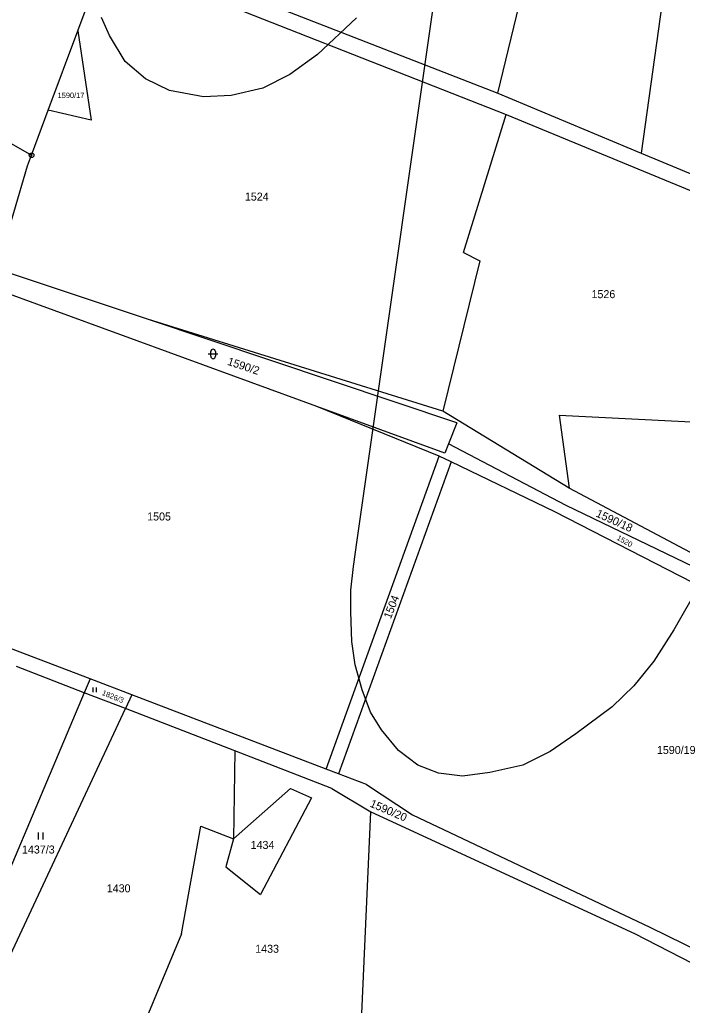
# Model space of a CAD drawing. Extents: x -546762 to -540209, y -1046851 to -1035694.
# Drawn here: x -543447.5 to -543306.6, y -1041018.4 to -1040809.1 of the extents above; entities that cross this region are included whole.
import ezdxf

# ---------------------------------------------------------------- set-up
doc = ezdxf.new("R2010")
doc.units = 0
for name, color, linetype in [('Vrstva 1', 7, 'Continuous'), ('Vrstva 18', 7, 'Continuous'), ('Vrstva 24', 7, 'Continuous'), ('Vrstva 25', 7, 'Continuous'), ('Vrstva 52', 7, 'Continuous'), ('Vrstva 6', 7, 'Continuous')]:
    doc.layers.add(name, color=color, linetype=linetype)

msp = doc.modelspace()

# ---------------------------------------------------------------- linework, layer by layer
at = {"layer": 'Vrstva 1'}
for points in [[(-543435.13, -1040811.43), (-543428.68, -1040794.07)], [(-543441.39, -1040828.27), (-543435.13, -1040811.43)], [(-543473.34, -1040821.64), (-543444.94, -1040837.84)], [(-543444.94, -1040837.84), (-543441.39, -1040828.27)], [(-543445.79, -1040840.11), (-543444.94, -1040837.84)], [(-543451.66, -1040859.91), (-543445.79, -1040840.11)], [(-543420.32, -1040872.69), (-543452.28, -1040862.01)], [(-543384.31, -1040891.22), (-543454.19, -1040865.7)], [(-543354.57, -1040894.66), (-543420.32, -1040872.69)], [(-543357.1, -1040901.15), (-543384.31, -1040891.22)], [(-543354.57, -1040894.66), (-543356.32, -1040899.16)], [(-543356.32, -1040899.16), (-543357.1, -1040901.15)], [(-543432.51, -1040949.06), (-543456.92, -1040939.75)], [(-543433.75, -1040951.99), (-543448.12, -1040946.45)], [(-543432.51, -1040949.06), (-543433.75, -1040951.99)], [(-543423.63, -1040952.45), (-543432.51, -1040949.06)], [(-543433.75, -1040951.99), (-543460.13, -1041014.34)], [(-543425, -1040955.37), (-543433.75, -1040951.99)], [(-543423.63, -1040952.45), (-543425, -1040955.37)], [(-543454.04, -1041017.4), (-543425, -1040955.37)]]:
    msp.add_lwpolyline(points, dxfattribs=at)
at = {"layer": 'Vrstva 24'}
for radius in [0.5, 0.1]:
    msp.add_circle((-543444.94, -1040837.84), radius, dxfattribs=at)
at = {"layer": 'Vrstva 25'}
for p, q in [((-543407.38, -1040880.05), (-543405.38, -1040880.05)), ((-543406.88, -1040880.55), (-543406.88, -1040879.55)), ((-543405.88, -1040879.55), (-543405.88, -1040880.55)), ((-543431.84, -1040951.91), (-543431.84, -1040950.91)), ((-543431.18, -1040951.91), (-543431.18, -1040950.91)), ((-543443.49, -1040983.2), (-543443.49, -1040981.7)), ((-543442.49, -1040983.2), (-543442.49, -1040981.7))]:
    msp.add_line(p, q, dxfattribs=at)
for centre, start, end in [((-543406.38, -1040879.55), 0, 180), ((-543406.38, -1040880.55), 180, 0)]:
    msp.add_arc(centre, 0.5, start, end, dxfattribs=at)
at = {"layer": 'Vrstva 52'}
for points in [[(-543303.12, -1040929.34), (-543308.45, -1040938.67), (-543312.69, -1040945.33), (-543316.93, -1040950.54), (-543321.53, -1040955.03), (-543329.28, -1040960.72), (-543334.73, -1040964.48), (-543340.54, -1040967.39), (-543347.57, -1040968.96), (-543353.38, -1040969.69), (-543358.47, -1040969.08), (-543362.83, -1040967.39), (-543366.94, -1040964.24), (-543370.58, -1040959.87), (-543372.88, -1040956.12), (-543374.69, -1040951.39), (-543376.15, -1040946.06), (-543376.87, -1040941.09), (-543377.12, -1040934.79), (-543377.12, -1040930.19), (-543376.51, -1040925.22), (-543375.75, -1040919.57), (-543356.78, -1040786.63)], [(-543375.91, -1040808.69), (-543384.15, -1040816.44), (-543390.08, -1040820.68), (-543395.78, -1040823.59), (-543402.56, -1040825.17), (-543408.37, -1040825.41), (-543415.64, -1040824.08), (-543420.72, -1040821.65), (-543425.08, -1040817.9), (-543428.35, -1040812.44), (-543430.05, -1040808.57)]]:
    msp.add_lwpolyline(points, dxfattribs=at)
at = {"layer": 'Vrstva 6'}
for points in [[(-543345.87, -1040824.69), (-543328.21, -1040751.86)], [(-543304.84, -1040761.68), (-543315.35, -1040837.41)], [(-543420.75, -1040795.46), (-543345.87, -1040824.69)], [(-543420.93, -1040798.94), (-543344.09, -1040829.21)], [(-543435.13, -1040811.43), (-543432.28, -1040830.42)], [(-543345.87, -1040824.69), (-543315.35, -1040837.41)], [(-543432.28, -1040830.42), (-543441.39, -1040828.27)], [(-543353.18, -1040858.52), (-543344.09, -1040829.21)], [(-543344.09, -1040829.21), (-543288.97, -1040851.94)], [(-543315.35, -1040837.41), (-543287.43, -1040849.04)], [(-543353.18, -1040858.52), (-543349.67, -1040860.25)], [(-543349.67, -1040860.25), (-543357.56, -1040892.17)], [(-543357.56, -1040892.17), (-543420.32, -1040872.69)], [(-543358.35, -1040901.76), (-543384.31, -1040891.22)], [(-543330.72, -1040908.55), (-543357.56, -1040892.17)], [(-543332.83, -1040893.08), (-543300.49, -1040894.65)], [(-543332.83, -1040893.08), (-543330.72, -1040908.55)], [(-543331.36, -1040912.26), (-543356.32, -1040899.16)], [(-543382.32, -1040968.22), (-543358.35, -1040901.76)], [(-543355.78, -1040902.99), (-543358.35, -1040901.76)], [(-543355.78, -1040902.99), (-543379.72, -1040969.22)], [(-543333.73, -1040913.56), (-543355.78, -1040902.99)], [(-543290.9, -1040929.66), (-543330.72, -1040908.55)], [(-543292.63, -1040930.87), (-543331.36, -1040912.26)], [(-543296.36, -1040932.78), (-543333.73, -1040913.56)], [(-543382.32, -1040968.22), (-543423.63, -1040952.45)], [(-543401.78, -1040964.34), (-543425, -1040955.37)], [(-543401.78, -1040964.34), (-543402, -1040983)], [(-543381.15, -1040972.31), (-543401.78, -1040964.34)], [(-543379.72, -1040969.22), (-543382.32, -1040968.22)], [(-543373.74, -1040971.5), (-543379.72, -1040969.22)], [(-543402, -1040983), (-543389.93, -1040972.34)], [(-543389.93, -1040972.34), (-543385.47, -1040974.34)], [(-543381.15, -1040972.31), (-543372.85, -1040977.28)], [(-543373.74, -1040971.5), (-543363.95, -1040977.93)], [(-543385.47, -1040974.34), (-543396.3, -1040994.84)], [(-543374.73, -1041020.11), (-543372.85, -1040977.28)], [(-543372.85, -1040977.28), (-543316.78, -1041003.12)], [(-543363.95, -1040977.93), (-543313.56, -1041001.76)], [(-543413.07, -1041003.19), (-543408.97, -1040980.37)], [(-543408.97, -1040980.37), (-543402, -1040983)], [(-543402, -1040983), (-543403.63, -1040988.99)], [(-543403.63, -1040988.99), (-543396.3, -1040994.84)], [(-543313.56, -1041001.76), (-543277.16, -1041019.66)], [(-543413.07, -1041003.19), (-543425.02, -1041031.98)], [(-543316.78, -1041003.12), (-543279.73, -1041022.2)]]:
    msp.add_lwpolyline(points, dxfattribs=at)

# ---------------------------------------------------------------- texts
at = {"layer": 'Vrstva 18'}
for s, height, p in [('1590/17', 1.14, (-543439.41, -1040825.69)), ('1524', 1.7, (-543399.61, -1040847.48)), ('1526', 1.7, (-543325.94, -1040868.2)), ('1505', 1.7, (-543420.38, -1040915.42)), ('1590/19', 1.7, (-543312.04, -1040965.01)), ('1434', 1.7, (-543398.39, -1040985.18)), ('1437/3', 1.7, (-543446.99, -1040986.15)), ('1430', 1.7, (-543428.97, -1040994.39)), ('1433', 1.7, (-543397.42, -1041007.23))]:
    msp.add_text(s, height=height, dxfattribs=at).set_placement(p)
for s, height, rotation, p in [('1590/2', 1.7, 341.65, (-543403.45, -1040882.32)), ('1590/18', 1.7, 335.4106, (-543325.15, -1040914.52)), ('1520', 1.14, 331.1179, (-543320.69, -1040919.45)), ('1504', 1.7, 68.7036, (-543368.6, -1040936.44)), ('1826/3', 1.14, 337.9903, (-543430.1, -1040952.43)), ('1590/20', 1.7, 336.6702, (-543373.18, -1040976.15))]:
    msp.add_text(s, height=height, rotation=rotation, dxfattribs=at).set_placement(p)

doc.saveas('drawing.dxf')
